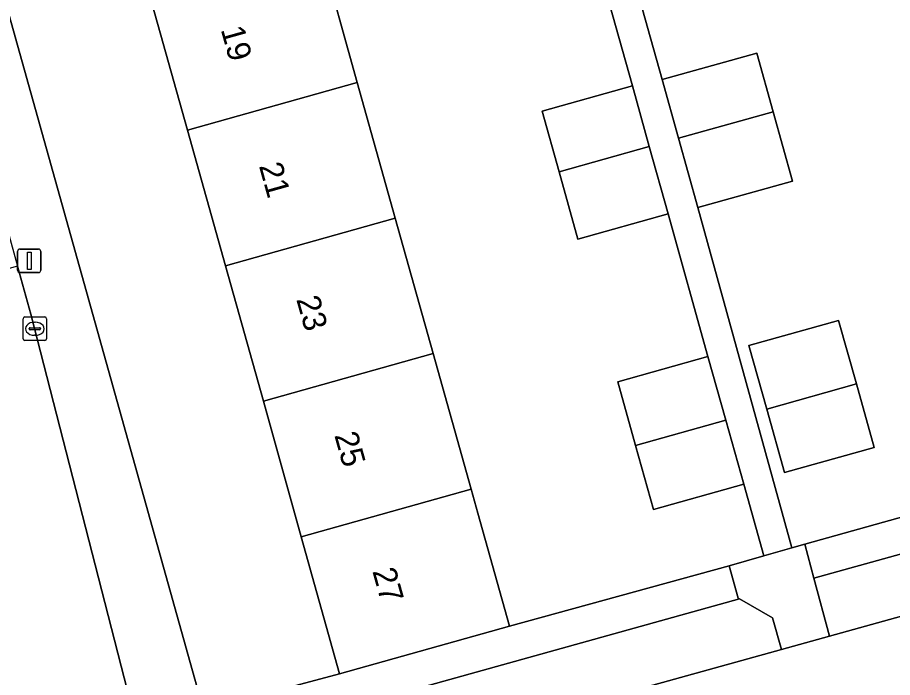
# Model space of a CAD drawing. Extents: x 159053 to 160042, y 380449 to 381423.
# Drawn here: x 159233.77 to 159271.09, y 380938.33 to 380966.47 of the extents above; entities that cross this region are included whole.
import ezdxf

# ---------------------------------------------------------------- set-up
doc = ezdxf.new("R2010")
doc.units = 0
for name, color, linetype in [('IMGEO_Erf', 7, 'Continuous'), ('IMGEO_Groenvoorziening', 7, 'Continuous'), ('IMGEO_Kolk', 7, 'Continuous'), ('IMGEO_Lichtmast', 7, 'Continuous'), ('IMGEO_Pand', 7, 'Continuous'), ('IMGEO_Pand_nummerreeks', 7, 'Continuous'), ('IMGEO_Rijbaan_lokaal_open', 7, 'Continuous'), ('IMGEO_Voetpad_open', 7, 'Continuous')]:
    doc.layers.add(name, color=color, linetype=linetype)

msp = doc.modelspace()

# ---------------------------------------------------------------- linework, layer by layer
at = {"layer": 'IMGEO_Erf'}
for points in [[(159247.51, 380938.496), (159245.875, 380944.333), (159244.257, 380950.11), (159242.639, 380955.888), (159241.02, 380961.666), (159239.402, 380967.443), (159237.784, 380973.221), (159236.148, 380979.061), (159238.277, 380979.658), (159237.431, 380982.682), (159236.585, 380985.703), (159234.433, 380985.1), (159232.797, 380990.974), (159231.186, 380996.755), (159230.282, 381000), (159229.576, 381002.534), (159227.965, 381008.314), (159226.355, 381014.094), (159224.744, 381019.874), (159223.107, 381025.75), (159217.284, 381024.142), (159224.043, 381000), (159241.698, 380936.943)], [(159268.794, 380953.557), (159269.553, 380950.849), (159270.311, 380948.141), (159266.487, 380947.07), (159265.728, 380949.778), (159264.97, 380952.486)]]:
    msp.add_lwpolyline(points, close=True, dxfattribs=at)
for points in [[(159251.483, 380999.442), (159253.968, 380990.169), (159258.084, 380991.313), (159258.818, 380988.673), (159259.605, 380985.839), (159255.49, 380984.696), (159258.05, 380975.387), (159262.096, 380976.513), (159262.786, 380974.011), (159263.611, 380971.018), (159259.562, 380969.902), (159261.267, 380963.827), (159265.305, 380964.951), (159266, 380962.452), (159266.823, 380959.496), (159262.784, 380958.373), (159266.796, 380943.855), (159267.352, 380944.011), (159278.291, 380947.073)], [(159246.646, 380969.472), (159248.264, 380963.695), (159249.882, 380957.917), (159251.501, 380952.139), (159253.119, 380946.362), (159253.405, 380945.34), (159254.754, 380940.525), (159264.121, 380943.101), (159265.611, 380943.521), (159264.751, 380946.575), (159260.9, 380945.496), (159260.137, 380948.22), (159259.374, 380950.944), (159263.224, 380952.023), (159261.524, 380958.099), (159257.673, 380957.02), (159256.871, 380959.884), (159256.147, 380962.468), (159259.997, 380963.547), (159258.296, 380969.625)]]:
    msp.add_lwpolyline(points, dxfattribs=at)
at = {"layer": 'IMGEO_Groenvoorziening'}
for points in [[(159289.244, 380950.092), (159285.477, 380949.072), (159278.291, 380947.073), (159267.352, 380944.011), (159267.741, 380942.562), (159289.412, 380948.582)], [(159289.412, 380948.582), (159267.741, 380942.562), (159268.403, 380940.097), (159286.78, 380945.193)], [(159242.353, 380935.51), (159264.567, 380941.681), (159264.514, 380941.711), (159264.121, 380943.101), (159254.754, 380940.525), (159247.51, 380938.496), (159241.698, 380936.943), (159241.77, 380936.7)], [(159246.921, 380934.139), (159266.365, 380939.531), (159265.98, 380940.881), (159264.567, 380941.681), (159242.353, 380935.51)]]:
    msp.add_lwpolyline(points, dxfattribs=at)
at = {"layer": 'IMGEO_Kolk'}
for p, q in [((159234.009, 380952.776), (159234.009, 380953.628)), ((159234.084, 380953.702), (159234.936, 380953.702)), ((159234.497, 380953.482), (159234.522, 380953.482)), ((159235.01, 380953.628), (159235.01, 380952.776)), ((159234.268, 380953.196), (159234.268, 380953.208)), ((159234.706, 380953.159), (159234.308, 380953.159)), ((159234.311, 380953.245), (159234.709, 380953.245)), ((159234.752, 380953.208), (159234.752, 380953.196)), ((159234.52, 380952.922), (159234.495, 380952.922)), ((159234.936, 380952.702), (159234.084, 380952.702))]:
    msp.add_line(p, q, dxfattribs=at)
for points in [[(159234.009, 380952.776), (159234.009, 380953.628)], [(159234.084, 380953.702), (159234.936, 380953.702)], [(159235.01, 380953.628), (159235.01, 380952.776)], [(159234.936, 380952.702), (159234.084, 380952.702)]]:
    msp.add_lwpolyline(points, dxfattribs=at)
for centre, radius, start, end in [((159234.086, 380953.626), 0.0765, 91.552, 178.448), ((159234.086, 380953.626), 0.0765, 91.552, 178.448), ((159234.934, 380953.626), 0.0765, 1.552, 88.448), ((159234.934, 380953.626), 0.0765, 1.552, 88.448), ((159234.308, 380953.205), 0.0403, 85.8775, 175.7526), ((159234.305, 380953.195), 0.0366, 178.938, 274.7102), ((159234.709, 380953.202), 0.043, 264.8664, 352.4533), ((159234.713, 380953.207), 0.0386, 1.7309, 96.639), ((159234.086, 380952.778), 0.0765, 181.552, 268.448), ((159234.086, 380952.778), 0.0765, 181.552, 268.448), ((159234.934, 380952.778), 0.0765, 271.552, 358.448), ((159234.934, 380952.778), 0.0765, 271.552, 358.448)]:
    msp.add_arc(centre, radius, start, end, dxfattribs=at)
for centre, major_axis, ratio, start_param, end_param in [((159234.496, 380953.202), (-0.387, 0.002), 0.722429, 4.712389, 7.853982), ((159234.521, 380953.202), (-0.39, 0.002), 0.717154, 1.570796, 4.712389)]:
    msp.add_ellipse(centre, major_axis=major_axis, ratio=ratio, start_param=start_param, end_param=end_param, dxfattribs=at)
at = {"layer": 'IMGEO_Lichtmast'}
for p, q in [((159233.776, 380955.695), (159233.776, 380956.495)), ((159233.776, 380956.495), (159233.776, 380955.695)), ((159233.876, 380956.595), (159234.666, 380956.595)), ((159234.666, 380956.595), (159233.876, 380956.595)), ((159234.766, 380956.495), (159234.766, 380955.695)), ((159234.766, 380955.695), (159234.766, 380956.495)), ((159234.666, 380955.595), (159233.876, 380955.595)), ((159233.876, 380955.595), (159234.666, 380955.595))]:
    msp.add_line(p, q, dxfattribs=at)
msp.add_lwpolyline([(159234.196, 380956.47), (159234.346, 380956.47), (159234.346, 380955.72), (159234.196, 380955.72), (159234.196, 380956.47)], dxfattribs=at)
for centre, start, end in [((159233.876, 380956.495), 90, 180), ((159233.876, 380956.495), 90, 180), ((159234.666, 380956.495), 0, 90), ((159234.666, 380956.495), 360, 90), ((159233.876, 380955.695), 180, 270), ((159233.876, 380955.695), 180, 270), ((159234.666, 380955.695), 270, 0), ((159234.666, 380955.695), 270, 0)]:
    msp.add_arc(centre, 0.1, start, end, dxfattribs=at)
at = {"layer": 'IMGEO_Pand'}
for points in [[(159248.264, 380963.695), (159246.646, 380969.472), (159239.402, 380967.443), (159241.02, 380961.666)], [(159261.267, 380963.827), (159261.962, 380961.329), (159266, 380962.452), (159265.305, 380964.951)], [(159248.264, 380963.695), (159241.02, 380961.666), (159242.639, 380955.888), (159249.882, 380957.917)], [(159256.871, 380959.884), (159260.721, 380960.963), (159259.997, 380963.547), (159256.147, 380962.468)], [(159266, 380962.452), (159261.962, 380961.329), (159262.784, 380958.373), (159266.823, 380959.496)], [(159256.871, 380959.884), (159257.673, 380957.02), (159261.524, 380958.099), (159260.721, 380960.963)], [(159249.882, 380957.917), (159242.639, 380955.888), (159244.257, 380950.11), (159251.501, 380952.139)], [(159268.794, 380953.557), (159264.97, 380952.486), (159265.728, 380949.778), (159269.553, 380950.849)], [(159245.875, 380944.333), (159253.119, 380946.362), (159251.501, 380952.139), (159244.257, 380950.11)], [(159260.137, 380948.22), (159263.988, 380949.299), (159263.224, 380952.023), (159259.374, 380950.944)], [(159270.311, 380948.141), (159269.553, 380950.849), (159265.728, 380949.778), (159266.487, 380947.07)], [(159260.137, 380948.22), (159260.9, 380945.496), (159264.751, 380946.575), (159263.988, 380949.299)], [(159245.875, 380944.333), (159247.51, 380938.496), (159254.754, 380940.525), (159253.405, 380945.34), (159253.119, 380946.362)]]:
    msp.add_lwpolyline(points, close=True, dxfattribs=at)
at = {"layer": 'IMGEO_Rijbaan_lokaal_open'}
msp.add_lwpolyline([(159239.173, 380934.996), (159238.874, 380936.156), (159234.335, 380953.821), (159233.764, 380955.863), (159227.067, 380953.987), (159231.034, 380939.757), (159232.538, 380934.356), (159232.744, 380933.615)], dxfattribs=at)
at = {"layer": 'IMGEO_Voetpad_open'}
for points in [[(159217.284, 381024.142), (159216.867, 381025.644), (159214.295, 381024.942), (159219.206, 381008.024), (159220.402, 381003.72), (159221.152, 381001.023), (159221.437, 381000), (159222.598, 380995.644), (159227.69, 380977.591), (159233.01, 380958.559), (159233.764, 380955.863), (159234.335, 380953.821), (159238.874, 380936.156), (159241.698, 380936.943), (159224.043, 381000)], [(159267.741, 380942.562), (159267.352, 380944.011), (159266.796, 380943.855), (159265.611, 380943.521), (159264.121, 380943.101), (159264.514, 380941.711), (159264.567, 380941.681), (159265.98, 380940.881), (159266.365, 380939.531), (159268.403, 380940.097)]]:
    msp.add_lwpolyline(points, close=True, dxfattribs=at)
for points in [[(159258.296, 380969.625), (159259.997, 380963.547), (159260.721, 380960.963), (159261.524, 380958.099), (159263.224, 380952.023), (159263.988, 380949.299), (159264.751, 380946.575), (159265.611, 380943.521), (159266.796, 380943.855), (159262.784, 380958.373), (159261.962, 380961.329), (159261.267, 380963.827), (159259.562, 380969.902)], [(159293.632, 380947.093), (159286.78, 380945.193), (159268.403, 380940.097), (159266.365, 380939.531), (159246.921, 380934.139)]]:
    msp.add_lwpolyline(points, dxfattribs=at)

# ---------------------------------------------------------------- texts
at = {"layer": 'IMGEO_Pand_nummerreeks'}
for s, p in [('19', (159242.434, 380965.961)), ('21', (159244.064, 380960.145)), ('23', (159245.656, 380954.459)), ('25', (159247.279, 380948.664)), ('27', (159248.902, 380942.869))]:
    msp.add_text(s, height=1, rotation=285.6472, dxfattribs=at).set_placement(p)

doc.saveas('drawing.dxf')
